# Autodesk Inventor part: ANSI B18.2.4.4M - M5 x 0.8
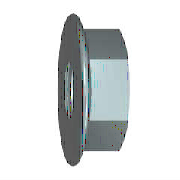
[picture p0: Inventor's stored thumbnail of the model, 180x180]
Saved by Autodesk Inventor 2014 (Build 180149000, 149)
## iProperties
IsCustomPart: 0
Created: 2008-02
Part Number: ANSI B18.2.4.4M - M5 x 0.8
Material: Steel, Mild
Description: Metric Hex Flange Nut
Document SubType Name: Modeling
Standard: ANSI B18.2.4.4M
Designer: PN
Standard Revision: 1999
Standards Organization: ANSI
Language: en-US
Size Designation: M5 x 0.8
Categories: <MemberInstance><Categories><Category DisplayName="Fasteners" InternalName="e4da775c-781d-43d5-af7c-5136215cf5a6" Mnemonic="FSTN"><Category DisplayName="Nuts" I
Density: 7.86 g/cm^3
Mass: 2.42166 g
Surface Area: 3.62968 cm^2
Volume: 0.308099 cm^3
Appearance: Steel
Author: PN
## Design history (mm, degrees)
sketch "Sketch1"
  geometry: L1 (-1.23, 0)-(6.038, 0) reference; L2 (2.674, 4)-(1.866, 5.4); L3 (2.674, 4)-(5, 4); L4 (5, 4)-(5, 0); L5 (2.674, 4)-(2.674, 0); L6 (0, -1.223)-(0, 7.339) reference; A1 r 1 centre (1, 4.9) between (1.866, 5.4) and (0, 4.9); 1 further point
  constraints: 8 end point, 3 point on line, 2 perpendicular, 2 point on circle, 2 tangent, 1 centre point, 1 parallel
  dimensions: "d2" = 8 diameter of L3 L1 (= SW); "d4" = 11.8 dimension on A1 L1 (= LADI); "d5" = 1 radius of A1 (= PHH); "d15" = 5 distance between parallel lines of L4 L6 (= KOH); "d16" = 30 deg angle of L6 L2 (= KEWI)
revolve "Ring" sketch "Sketch1" stored, may be unused: angle "d8" = 90 deg
sketch "Sketch2"
  geometry: L1 (-4, -2.309)-(-4, 2.309); L2 (-4, 2.309)-(0, 4.619); L3 (0, 4.619)-(4, 2.309); L4 (4, 2.309)-(4, -2.309); L5 (4, -2.309)-(0, -4.619); L6 (0, -4.619)-(-4, -2.309); C1 r 4.9 at (0, 0); C2 r 4.9 at (0, 0) reference; 1 further point
  constraints: 12 end point, 1 centre point, 1 coincident, 1 vertical, 11 other
  dimensions: "d6" = 9.2376 distance of L5.end L2.end (= 1.1547 x SW)
extrude "Body" join sketch "Sketch2" distance "d7" = 5 (= KOH); taper "d9" = 0 deg
sketch "Sketch3"
  geometry: L1 (2.317, 4.619)-(5, 4.619) reference; L2 (5, 2.309)-(5, 4.619) reference; L3 (0, -4.9)-(0, 4.9) reference; L4 (-1, 0)-(6, 0) reference; L5 (4.643, 4.619)-(5, 4)
  constraints: 2 end point, 2 point on line
  dimensions: "d10" = 30 deg angle of L2 L5 (= ANG1); "d11" = 8 diameter of L5.end L4 (= SW0)
revolve "Chamfer1" sketch "Sketch3" stored, may be unused: angle "d24" = 90 deg
sketch "Sketch4"
  geometry: C1 r 4.9 at (0, 0) reference; 1 further point
  constraints: 1 coincident
hole "Thread" sketch "Sketch4" at (0, 0) diameter "d25" = 4.134; stored, may be unused: countersink angle "d29" = 82 deg, drill point angle "d31" = 118 deg; dims "d26" = 6, "d27" = 4, "d28" = 2, "d30" = 8
workaxis "Work Axis1"
workplane "Work Plane1"
body "Solid1"
chamfer "Chamfer2" distance "d12" = 0.43301 (= -0.5 x GD1 + 0.5 x NND); stored, may be unused: angle "d13" = 30 deg, second distance "d46" = 0.43301 (= -0.5 x GD1 + 0.5 x NND)
chamfer "Chamfer3" distance "d51" = 0.43301 (= -0.5 x GD1 + 0.5 x NND); stored, may be unused: second distance "d52" = 2, angle "d53" = 45 deg
other parameters: "ANG1" = 30 deg [user parameter; used in 1 equation term], "KEWI" = 30 deg [user parameter; used in 1 equation term], "NND" = 5 [user parameter; used in 3 equation terms], "LADI" = 11.8 [user parameter; used in 2 equation terms], "SW" = 8 [user parameter; used in 4 equation terms], "PHH" = 1 (= RR) [user parameter; used in 2 equation terms], "KOH" = 5 [user parameter; used in 2 equation terms], "SW0" = 8 (= SW) [user parameter; used in 1 equation term], "GD1" = 4.13397 (computed from THREADDIA, PTC, TOA) [user parameter; used in 3 equation terms], "d1" = 11.8 (= LADI), "d3" = 1 (= PHH), "d45" = 0, "d47" = 0, "d49" = 0, "d54" = 0, "GUL" = 0.43301 (= 0.541266 x PTC) [user parameter], "TPU" = 12.5 (computed from PTC) [user parameter], "RR" = 1 [user parameter; used in 1 equation term], "THREADDIA" = 5 [user parameter; used in 1 equation term], "TOA" = 30 deg [user parameter; used in 1 equation term], "PTC" = 0.8 [user parameter; used in 4 equation terms], "RR1" = 0.3 [user parameter], "GAL" = 0.43301 (= 0.541266 x PTC) [user parameter], "E0" = 9.24 (= 1.155 x SW) [user parameter]
